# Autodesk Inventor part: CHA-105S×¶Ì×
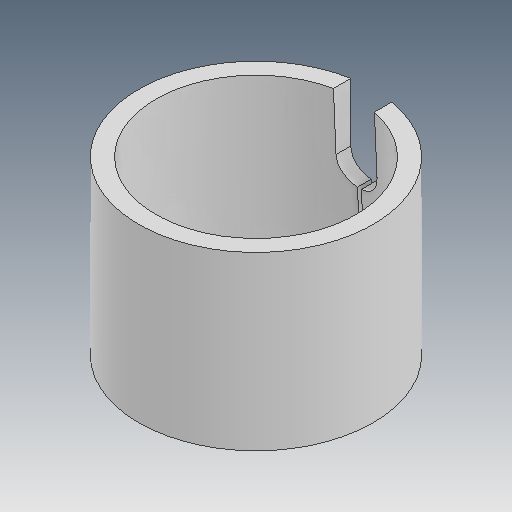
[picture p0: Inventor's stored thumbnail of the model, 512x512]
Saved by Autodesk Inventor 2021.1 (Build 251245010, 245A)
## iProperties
Created: 2019-12
Part Number: CHA-105S×¶Ì×
Material: Ogólny
Document SubType Name: Modeling
Designer: user
Density: 1 g/cm^3
Appearance: Domyślna
Author: user
Revision Number: ÈÎºÎ
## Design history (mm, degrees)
feature "ÊäÈë1"
node "Bryła1"
